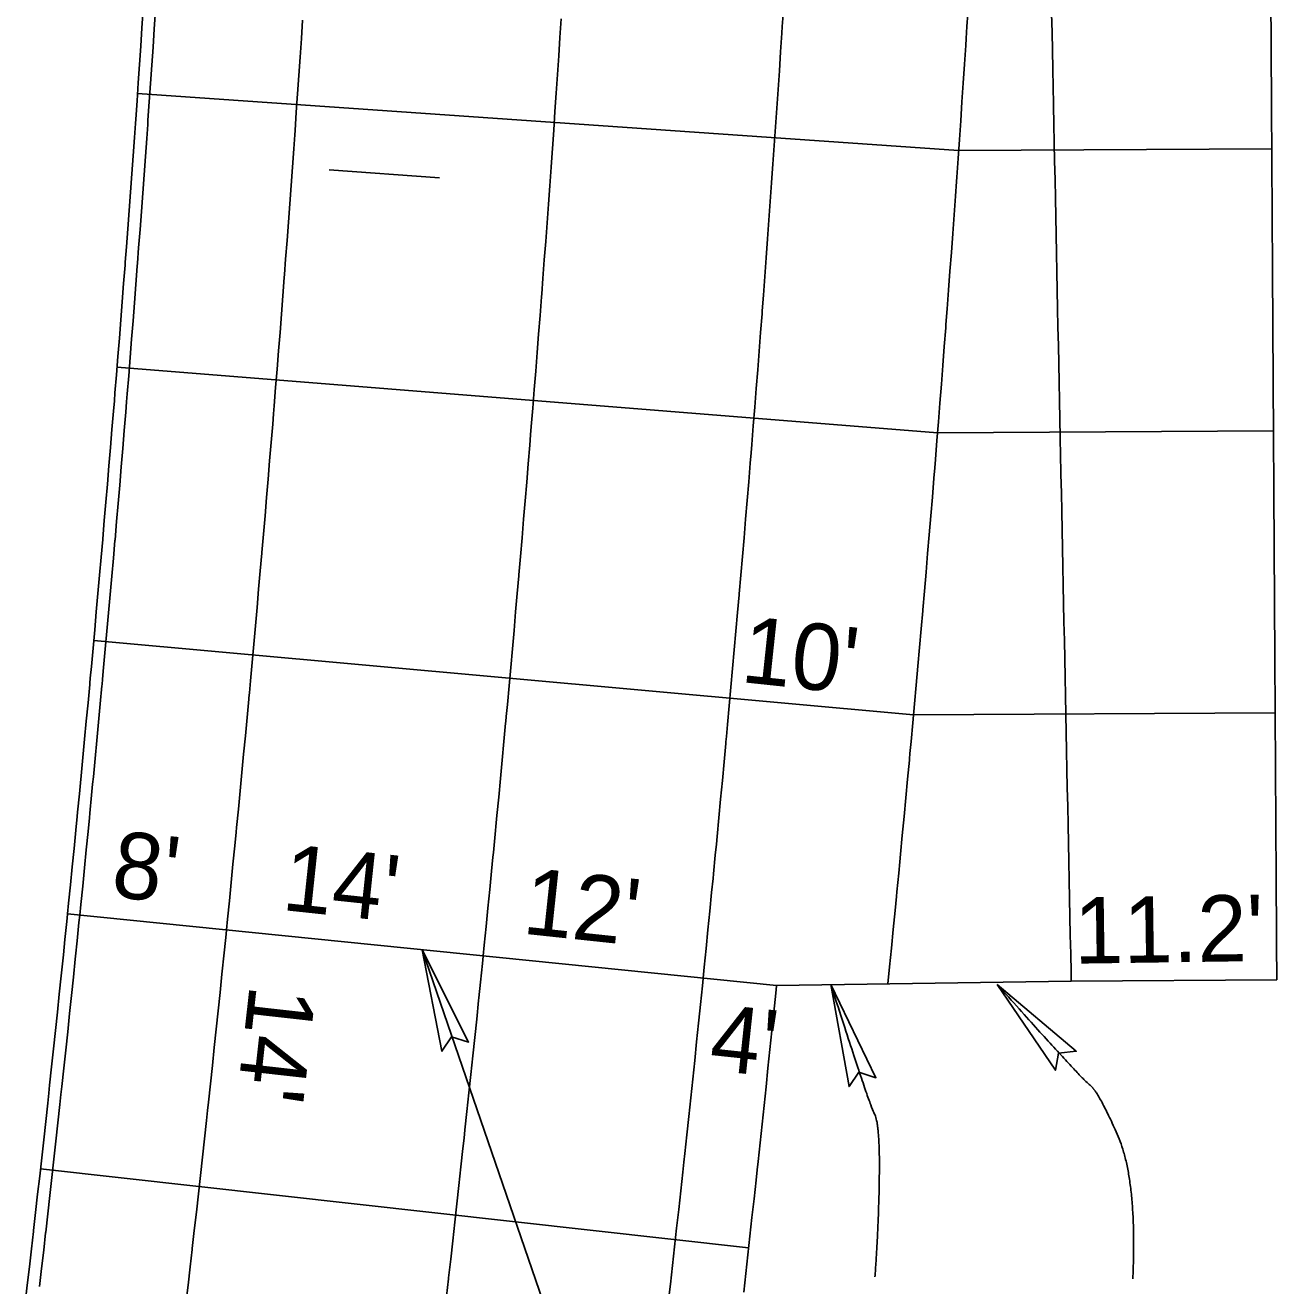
# Model space of a CAD drawing. Extents: x 2145147 to 2158018, y 137519 to 148068.
# Drawn here: x 2150700.2 to 2150768.1, y 144566.8 to 144635.2 of the extents above; entities that cross this region are included whole.
import ezdxf

# ---------------------------------------------------------------- set-up
doc = ezdxf.new("R2010")
doc.units = 0
for name, color, linetype in [('PR_Align_Ramp_B', 7, 'Continuous'), ('PR_Align_Service_C_Leader', 7, 'Continuous'), ('PR_Arrows', 7, 'Continuous'), ('PR_Dimensions', 7, 'Continuous'), ('PR_Joint_Contraction', 7, 'Continuous'), ('PR_Joint_Isolation', 7, 'Continuous'), ('PR_Joint_Long', 7, 'Continuous'), ('PR_Road_Concrete', 7, 'Continuous')]:
    doc.layers.add(name, color=color, linetype=linetype)

msp = doc.modelspace()

# ---------------------------------------------------------------- linework, layer by layer
at = {"layer": 'PR_Align_Ramp_B'}
msp.add_lwpolyline([(2150722.704, 144626.925), (2150716.719, 144627.356)], dxfattribs=at)
at = {"layer": 'PR_Align_Service_C_Leader'}
msp.add_lwpolyline([(2150721.757, 144585.051), (2150741.818, 144526.722), (2150741.818, 144492.692)], dxfattribs=at)
at = {"layer": 'PR_Arrows'}
msp.add_lwpolyline([(2150721.757, 144585.051), (2150722.84, 144579.543), (2150723.362, 144580.331), (2150724.288, 144580.045)], close=True, dxfattribs=at)
at = {"layer": 'PR_Dimensions'}
for points in [[(2150743.944, 144583.158), (2150744.929, 144577.631), (2150745.465, 144578.409), (2150746.386, 144578.107)], [(2150752.977, 144583.158), (2150756.128, 144578.512), (2150756.301, 144579.441), (2150757.264, 144579.541)]]:
    msp.add_lwpolyline(points, close=True, dxfattribs=at)
for points in [[(2150746.338, 144567.298), (2150746.554, 144570.37), (2150746.597, 144575.619), (2150746.028, 144576.653), (2150743.944, 144583.158)], [(2150760.329, 144567.205), (2150760.571, 144572.543), (2150758.471, 144577.354), (2150757.53, 144578.067), (2150752.977, 144583.158)]]:
    msp.add_open_spline(points, degree=2, dxfattribs=at)
at = {"layer": 'PR_Joint_Contraction'}
for p, q in [((2150750.878, 144628.401), (2150706.319, 144631.499)), ((2150750.878, 144628.401), (2150767.871, 144628.503)), ((2150749.733, 144613.087), (2150705.208, 144616.652)), ((2150749.733, 144613.087), (2150767.963, 144613.197)), ((2150748.427, 144597.787), (2150703.943, 144601.818)), ((2150748.427, 144597.787), (2150768.055, 144597.905)), ((2150739.483, 144568.888), (2150701.052, 144573.157))]:
    msp.add_line(p, q, dxfattribs=at)
at = {"layer": 'PR_Joint_Isolation'}
msp.add_line((2150740.992, 144583.105), (2150702.522, 144586.998), dxfattribs=at)
at = {"layer": 'PR_Joint_Long'}
for points in [[(2150741.351, 144635.778), (2150741.31, 144635.138), (2150741.285, 144634.763), (2150741.218, 144633.749), (2150741.151, 144632.734), (2150741.082, 144631.72), (2150741.013, 144630.705), (2150740.944, 144629.691), (2150740.873, 144628.677), (2150740.802, 144627.662), (2150740.785, 144627.426), (2150740.73, 144626.648), (2150740.657, 144625.634), (2150740.584, 144624.62), (2150740.51, 144623.606), (2150740.435, 144622.592), (2150740.36, 144621.578), (2150740.284, 144620.564), (2150740.22, 144619.717), (2150740.207, 144619.55), (2150740.129, 144618.536), (2150740.051, 144617.523), (2150739.972, 144616.509), (2150739.893, 144615.495), (2150739.812, 144614.482), (2150739.731, 144613.468), (2150739.649, 144612.455), (2150739.613, 144612.011), (2150739.567, 144611.441), (2150739.484, 144610.428), (2150739.4, 144609.415), (2150739.315, 144608.401), (2150739.23, 144607.388), (2150739.144, 144606.375), (2150739.057, 144605.362), (2150738.97, 144604.349), (2150738.966, 144604.308), (2150738.881, 144603.336), (2150738.793, 144602.323), (2150738.703, 144601.311), (2150738.613, 144600.298), (2150738.522, 144599.285), (2150738.43, 144598.273), (2150738.338, 144597.26), (2150738.278, 144596.609), (2150738.251, 144596.32), (2150738.244, 144596.247), (2150738.151, 144595.235), (2150738.056, 144594.223), (2150737.961, 144593.21), (2150737.865, 144592.198), (2150737.768, 144591.186), (2150737.729, 144590.781), (2150737.671, 144590.174), (2150737.573, 144589.162), (2150737.549, 144588.913), (2150737.474, 144588.15), (2150737.375, 144587.138), (2150737.275, 144586.126), (2150737.174, 144585.115), (2150737.072, 144584.103), (2150737.012, 144583.506), (2150737.011, 144583.496), (2150736.97, 144583.091), (2150736.867, 144582.08), (2150736.779, 144581.222), (2150736.763, 144581.068), (2150736.659, 144580.057), (2150736.554, 144579.046), (2150736.448, 144578.034), (2150736.341, 144577.023), (2150736.234, 144576.012), (2150736.126, 144575.001), (2150736.017, 144573.99), (2150735.968, 144573.534), (2150735.908, 144572.979), (2150735.798, 144571.969), (2150735.687, 144570.958), (2150735.576, 144569.947), (2150735.464, 144568.937), (2150735.351, 144567.926), (2150735.237, 144566.916), (2150735.123, 144565.906)], [(2150751.375, 144635.816), (2150751.33, 144635.13), (2150751.289, 144634.486), (2150751.264, 144634.107), (2150751.196, 144633.087), (2150751.128, 144632.065), (2150751.059, 144631.044), (2150750.99, 144630.023), (2150750.92, 144629.001), (2150750.849, 144627.98), (2150750.777, 144626.96), (2150750.76, 144626.72), (2150750.705, 144625.937), (2150750.632, 144624.917), (2150750.558, 144623.895), (2150750.483, 144622.874), (2150750.408, 144621.854), (2150750.332, 144620.833), (2150750.256, 144619.812), (2150750.191, 144618.96), (2150750.178, 144618.789), (2150750.1, 144617.77), (2150750.021, 144616.749), (2150749.942, 144615.729), (2150749.862, 144614.708), (2150749.781, 144613.688), (2150749.699, 144612.667), (2150749.617, 144611.648), (2150749.58, 144611.199), (2150749.534, 144610.626), (2150749.45, 144609.606), (2150749.365, 144608.586), (2150749.28, 144607.566), (2150749.194, 144606.546), (2150749.108, 144605.526), (2150749.02, 144604.506), (2150748.932, 144603.487), (2150748.928, 144603.442), (2150748.843, 144602.466), (2150748.754, 144601.446), (2150748.664, 144600.426), (2150748.573, 144599.406), (2150748.481, 144598.387), (2150748.389, 144597.367), (2150748.296, 144596.348), (2150748.236, 144595.692), (2150748.209, 144595.402), (2150748.202, 144595.327), (2150748.108, 144594.309), (2150748.013, 144593.29), (2150747.917, 144592.27), (2150747.82, 144591.251), (2150747.723, 144590.233), (2150747.684, 144589.824), (2150747.625, 144589.212), (2150747.526, 144588.195), (2150747.502, 144587.943), (2150747.427, 144587.175), (2150747.326, 144586.156), (2150747.226, 144585.138), (2150747.124, 144584.119), (2150747.031, 144583.195)], [(2150756.988, 144583.343), (2150756.978, 144583.833), (2150756.958, 144584.833), (2150756.937, 144585.833), (2150756.917, 144586.833), (2150756.897, 144587.833), (2150756.877, 144588.832), (2150756.856, 144589.832), (2150756.836, 144590.832), (2150756.816, 144591.832), (2150756.796, 144592.832), (2150756.775, 144593.832), (2150756.755, 144594.832), (2150756.735, 144595.832), (2150756.715, 144596.832), (2150756.694, 144597.832), (2150756.674, 144598.831), (2150756.654, 144599.831), (2150756.634, 144600.831), (2150756.613, 144601.831), (2150756.593, 144602.831), (2150756.573, 144603.831), (2150756.553, 144604.831), (2150756.532, 144605.831), (2150756.512, 144606.831), (2150756.492, 144607.83), (2150756.472, 144608.83), (2150756.451, 144609.83), (2150756.431, 144610.83), (2150756.428, 144610.989), (2150756.411, 144611.83), (2150756.391, 144612.83), (2150756.37, 144613.83), (2150756.35, 144614.83), (2150756.33, 144615.83), (2150756.309, 144616.83), (2150756.289, 144617.829), (2150756.269, 144618.829), (2150756.249, 144619.829), (2150756.228, 144620.829), (2150756.208, 144621.829), (2150756.188, 144622.829), (2150756.168, 144623.829), (2150756.147, 144624.829), (2150756.127, 144625.829), (2150756.107, 144626.829), (2150756.087, 144627.828), (2150756.066, 144628.828), (2150756.046, 144629.828), (2150756.026, 144630.828), (2150756.023, 144630.964), (2150756.006, 144631.828), (2150755.985, 144632.828), (2150755.965, 144633.828), (2150755.945, 144634.828), (2150755.925, 144635.828)], [(2150768.142, 144583.41), (2150768.139, 144583.9), (2150768.133, 144584.9), (2150768.127, 144585.9), (2150768.121, 144586.9), (2150768.115, 144587.9), (2150768.109, 144588.9), (2150768.103, 144589.9), (2150768.097, 144590.9), (2150768.091, 144591.9), (2150768.085, 144592.9), (2150768.079, 144593.9), (2150768.073, 144594.9), (2150768.067, 144595.9), (2150768.061, 144596.9), (2150768.055, 144597.9), (2150768.049, 144598.9), (2150768.043, 144599.9), (2150768.037, 144600.9), (2150768.031, 144601.9), (2150768.025, 144602.9), (2150768.019, 144603.9), (2150768.013, 144604.9), (2150768.007, 144605.9), (2150768.001, 144606.9), (2150767.995, 144607.9), (2150767.989, 144608.9), (2150767.983, 144609.9), (2150767.977, 144610.9), (2150767.976, 144611.059), (2150767.971, 144611.9), (2150767.965, 144612.9), (2150767.959, 144613.9), (2150767.953, 144614.899), (2150767.947, 144615.899), (2150767.941, 144616.899), (2150767.935, 144617.899), (2150767.929, 144618.899), (2150767.923, 144619.899), (2150767.917, 144620.899), (2150767.911, 144621.899), (2150767.905, 144622.899), (2150767.899, 144623.899), (2150767.893, 144624.899), (2150767.887, 144625.899), (2150767.881, 144626.899), (2150767.875, 144627.899), (2150767.869, 144628.899), (2150767.863, 144629.899), (2150767.857, 144630.899), (2150767.856, 144631.035), (2150767.851, 144631.899), (2150767.845, 144632.899), (2150767.839, 144633.899), (2150767.833, 144634.899), (2150767.827, 144635.899)], [(2150715.275, 144635.469), (2150715.209, 144634.473), (2150715.142, 144633.476), (2150715.074, 144632.48), (2150715.005, 144631.484), (2150714.936, 144630.488), (2150714.866, 144629.491), (2150714.85, 144629.259), (2150714.796, 144628.495), (2150714.724, 144627.499), (2150714.652, 144626.503), (2150714.58, 144625.507), (2150714.506, 144624.511), (2150714.432, 144623.516), (2150714.358, 144622.52), (2150714.294, 144621.687), (2150714.282, 144621.524), (2150714.206, 144620.528), (2150714.129, 144619.533), (2150714.051, 144618.537), (2150713.973, 144617.542), (2150713.894, 144616.546), (2150713.815, 144615.551), (2150713.734, 144614.555), (2150713.699, 144614.119), (2150713.653, 144613.56), (2150713.572, 144612.565), (2150713.489, 144611.57), (2150713.406, 144610.574), (2150713.322, 144609.579), (2150713.238, 144608.584), (2150713.153, 144607.589), (2150713.067, 144606.594), (2150713.063, 144606.554), (2150712.98, 144605.6), (2150712.893, 144604.605), (2150712.805, 144603.61), (2150712.716, 144602.615), (2150712.627, 144601.621), (2150712.537, 144600.626), (2150712.446, 144599.632), (2150712.387, 144598.992), (2150712.361, 144598.709), (2150712.355, 144598.638), (2150712.262, 144597.643), (2150712.17, 144596.649), (2150712.076, 144595.655), (2150711.982, 144594.66), (2150711.887, 144593.666), (2150711.849, 144593.269), (2150711.791, 144592.672), (2150711.695, 144591.678), (2150711.671, 144591.434), (2150711.598, 144590.685), (2150711.5, 144589.691), (2150711.402, 144588.697), (2150711.303, 144587.703), (2150711.203, 144586.71), (2150711.144, 144586.123), (2150711.143, 144586.114), (2150711.103, 144585.716), (2150711.001, 144584.723), (2150710.915, 144583.88), (2150710.9, 144583.73), (2150710.797, 144582.736), (2150710.694, 144581.743), (2150710.59, 144580.749), (2150710.485, 144579.756), (2150710.38, 144578.763), (2150710.274, 144577.77), (2150710.167, 144576.777), (2150710.119, 144576.33), (2150710.06, 144575.785), (2150709.952, 144574.792), (2150709.843, 144573.799), (2150709.733, 144572.807), (2150709.623, 144571.814), (2150709.512, 144570.822), (2150709.401, 144569.829), (2150709.289, 144568.837), (2150709.283, 144568.784), (2150709.176, 144567.845), (2150709.062, 144566.853), (2150708.948, 144565.861)], [(2150729.311, 144635.548), (2150729.245, 144634.543), (2150729.178, 144633.537), (2150729.11, 144632.53), (2150729.041, 144631.524), (2150728.972, 144630.518), (2150728.902, 144629.512), (2150728.832, 144628.508), (2150728.815, 144628.271), (2150728.76, 144627.5), (2150728.688, 144626.495), (2150728.616, 144625.489), (2150728.542, 144624.483), (2150728.468, 144623.478), (2150728.393, 144622.472), (2150728.318, 144621.467), (2150728.254, 144620.628), (2150728.242, 144620.459), (2150728.165, 144619.456), (2150728.087, 144618.45), (2150728.009, 144617.445), (2150727.93, 144616.44), (2150727.85, 144615.434), (2150727.77, 144614.429), (2150727.689, 144613.425), (2150727.653, 144612.983), (2150727.607, 144612.418), (2150727.524, 144611.414), (2150727.441, 144610.409), (2150727.357, 144609.404), (2150727.272, 144608.4), (2150727.187, 144607.395), (2150727.101, 144606.39), (2150727.015, 144605.387), (2150727.011, 144605.342), (2150726.927, 144604.381), (2150726.839, 144603.376), (2150726.75, 144602.372), (2150726.66, 144601.367), (2150726.57, 144600.363), (2150726.479, 144599.359), (2150726.388, 144598.355), (2150726.328, 144597.709), (2150726.302, 144597.423), (2150726.295, 144597.349), (2150726.202, 144596.346), (2150726.109, 144595.342), (2150726.014, 144594.338), (2150725.919, 144593.335), (2150725.823, 144592.332), (2150725.785, 144591.929), (2150725.726, 144591.326), (2150725.629, 144590.325), (2150725.605, 144590.075), (2150725.531, 144589.319), (2150725.433, 144588.316), (2150725.333, 144587.313), (2150725.233, 144586.309), (2150725.133, 144585.307), (2150725.073, 144584.715), (2150725.072, 144584.703), (2150725.031, 144584.302), (2150724.929, 144583.3), (2150724.842, 144582.45), (2150724.826, 144582.295), (2150724.723, 144581.293), (2150724.618, 144580.29), (2150724.513, 144579.288), (2150724.408, 144578.285), (2150724.301, 144577.282), (2150724.194, 144576.279), (2150724.087, 144575.278), (2150724.038, 144574.824), (2150723.978, 144574.273), (2150723.869, 144573.272), (2150723.759, 144572.269), (2150723.649, 144571.267), (2150723.537, 144570.265), (2150723.425, 144569.263), (2150723.313, 144568.261), (2150723.2, 144567.261), (2150723.193, 144567.203), (2150723.085, 144566.257)]]:
    msp.add_lwpolyline(points, dxfattribs=at)
at = {"layer": 'PR_Road_Concrete'}
for p in [(2150740.992, 144583.105), (2150768.142, 144583.41)]:
    msp.add_line(p, (2150756.988, 144583.343), dxfattribs=at)
for points in [[(2150707.293, 144635.998), (2150707.227, 144635.008), (2150707.16, 144634.017), (2150707.093, 144633.026), (2150707.024, 144632.035), (2150706.956, 144631.045), (2150706.886, 144630.054), (2150706.87, 144629.823), (2150706.816, 144629.064), (2150706.745, 144628.073), (2150706.673, 144627.083), (2150706.601, 144626.092), (2150706.528, 144625.102), (2150706.455, 144624.112), (2150706.38, 144623.122), (2150706.318, 144622.294), (2150706.305, 144622.131), (2150706.229, 144621.141), (2150706.153, 144620.151), (2150706.076, 144619.161), (2150705.998, 144618.171), (2150705.92, 144617.181), (2150705.84, 144616.191), (2150705.76, 144615.202), (2150705.725, 144614.768), (2150705.68, 144614.212), (2150705.599, 144613.222), (2150705.517, 144612.233), (2150705.434, 144611.243), (2150705.351, 144610.253), (2150705.267, 144609.264), (2150705.182, 144608.275), (2150705.097, 144607.285), (2150705.093, 144607.245), (2150705.01, 144606.296), (2150704.924, 144605.307), (2150704.836, 144604.318), (2150704.748, 144603.329), (2150704.659, 144602.339), (2150704.57, 144601.351), (2150704.479, 144600.362), (2150704.421, 144599.725), (2150704.395, 144599.444), (2150704.388, 144599.373), (2150704.297, 144598.384), (2150704.204, 144597.395), (2150704.111, 144596.407), (2150704.018, 144595.418), (2150703.923, 144594.429), (2150703.885, 144594.034), (2150703.828, 144593.441), (2150703.733, 144592.453), (2150703.709, 144592.21), (2150703.636, 144591.464), (2150703.539, 144590.476), (2150703.441, 144589.488), (2150703.343, 144588.5), (2150703.243, 144587.512), (2150703.185, 144586.929), (2150703.184, 144586.919), (2150703.143, 144586.524), (2150703.043, 144585.536), (2150702.957, 144584.698), (2150702.942, 144584.548), (2150702.84, 144583.56), (2150702.737, 144582.573), (2150702.634, 144581.585), (2150702.53, 144580.597), (2150702.425, 144579.61), (2150702.319, 144578.622), (2150702.213, 144577.635), (2150702.165, 144577.19), (2150702.107, 144576.648), (2150701.999, 144575.661), (2150701.891, 144574.674), (2150701.782, 144573.687), (2150701.672, 144572.7), (2150701.562, 144571.713), (2150701.451, 144570.726), (2150701.34, 144569.739), (2150701.334, 144569.686), (2150701.227, 144568.753), (2150701.114, 144567.766), (2150701.001, 144566.779)], [(2150706.628, 144636.043), (2150706.562, 144635.052), (2150706.495, 144634.062), (2150706.427, 144633.072), (2150706.359, 144632.081), (2150706.291, 144631.091), (2150706.221, 144630.101), (2150706.205, 144629.87), (2150706.151, 144629.111), (2150706.08, 144628.121), (2150706.009, 144627.131), (2150705.936, 144626.141), (2150705.863, 144625.151), (2150705.79, 144624.161), (2150705.715, 144623.172), (2150705.653, 144622.345), (2150705.64, 144622.182), (2150705.565, 144621.192), (2150705.488, 144620.203), (2150705.411, 144619.213), (2150705.333, 144618.224), (2150705.255, 144617.234), (2150705.176, 144616.245), (2150705.096, 144615.255), (2150705.061, 144614.822), (2150705.015, 144614.266), (2150704.934, 144613.277), (2150704.852, 144612.288), (2150704.77, 144611.299), (2150704.686, 144610.31), (2150704.602, 144609.321), (2150704.518, 144608.332), (2150704.432, 144607.343), (2150704.429, 144607.302), (2150704.346, 144606.354), (2150704.26, 144605.365), (2150704.172, 144604.377), (2150704.084, 144603.388), (2150703.995, 144602.399), (2150703.906, 144601.411), (2150703.815, 144600.422), (2150703.757, 144599.787), (2150703.731, 144599.505), (2150703.725, 144599.434), (2150703.633, 144598.446), (2150703.541, 144597.457), (2150703.448, 144596.469), (2150703.354, 144595.481), (2150703.26, 144594.493), (2150703.222, 144594.098), (2150703.165, 144593.505), (2150703.069, 144592.517), (2150703.045, 144592.274), (2150702.973, 144591.529), (2150702.876, 144590.542), (2150702.778, 144589.554), (2150702.679, 144588.566), (2150702.58, 144587.579), (2150702.521, 144586.996)], [(2150702.52, 144586.986), (2150702.48, 144586.591), (2150702.38, 144585.604), (2150702.294, 144584.766), (2150702.278, 144584.616), (2150702.177, 144583.629), (2150702.074, 144582.642), (2150701.971, 144581.655), (2150701.867, 144580.667), (2150701.762, 144579.68), (2150701.657, 144578.693), (2150701.551, 144577.707), (2150701.502, 144577.262), (2150701.444, 144576.72), (2150701.336, 144575.733), (2150701.228, 144574.746), (2150701.119, 144573.76), (2150701.01, 144572.773), (2150700.9, 144571.787), (2150700.789, 144570.801), (2150700.677, 144569.814), (2150700.671, 144569.762), (2150700.565, 144568.828), (2150700.452, 144567.842), (2150700.338, 144566.856), (2150700.224, 144565.87)], [(2150740.992, 144583.105), (2150740.99, 144583.093), (2150740.949, 144582.688), (2150740.846, 144581.673), (2150740.758, 144580.813), (2150740.742, 144580.659), (2150740.637, 144579.645), (2150740.532, 144578.631), (2150740.426, 144577.617), (2150740.319, 144576.603), (2150740.212, 144575.589), (2150740.103, 144574.575), (2150739.994, 144573.561), (2150739.945, 144573.104), (2150739.885, 144572.548), (2150739.774, 144571.534), (2150739.663, 144570.521), (2150739.551, 144569.507), (2150739.439, 144568.494), (2150739.326, 144567.481), (2150739.212, 144566.468)]]:
    msp.add_lwpolyline(points, dxfattribs=at)

# ---------------------------------------------------------------- texts
at = {"layer": 'PR_Dimensions'}
for s, rotation, p in [("10'", 353.92481, (2150738.998, 144599.578)), ("8'", 353.92481, (2150704.83, 144587.941)), ("14'", 353.92481, (2150714.094, 144587.214)), ("12'", 353.92481, (2150727.153, 144585.931)), ("11.2'", 0.81931, (2150757.163, 144584.293)), ("14'", 263.61742, (2150712.416, 144583.212)), ("4'", 353.92481, (2150737.282, 144578.534))]:
    msp.add_text(s, height=3.6, rotation=rotation, dxfattribs=at).set_placement(p)

doc.saveas('drawing.dxf')
